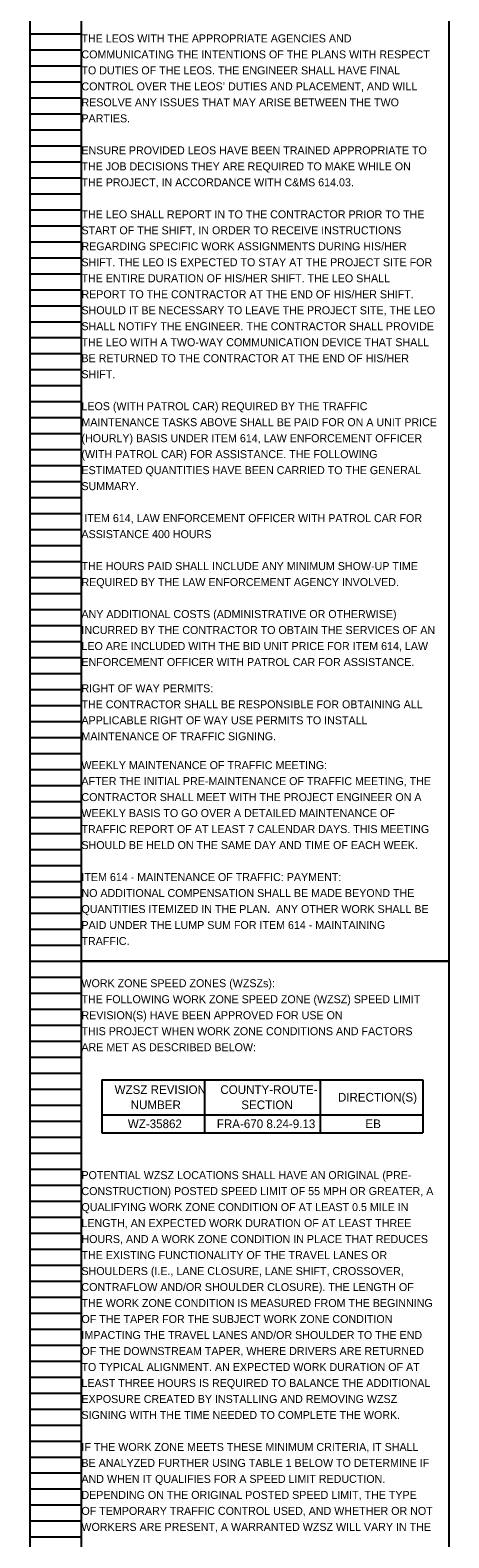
# Model space of a CAD drawing. Extents: x 16463 to 16500, y 5400 to 5823.
# Drawn here: x 16463.05 to 16470.39, y 5611.78 to 5638.18 of the extents above; entities that cross this region are included whole.
import ezdxf

# ---------------------------------------------------------------- set-up
doc = ezdxf.new("R2010")
doc.units = 0
for name, color, linetype in [('Default', 7, 'Continuous'), ('SC_Scratch1', 7, 'Continuous'), ('SH_Data', 7, 'Continuous')]:
    doc.layers.add(name, color=color, linetype=linetype)

msp = doc.modelspace()

# ---------------------------------------------------------------- linework, layer by layer
at = {"layer": 'Default'}
for p, q in [((16464.308, 5619.799), (16469.933, 5619.799)), ((16464.308, 5619.799), (16464.308, 5618.869)), ((16466.108, 5619.799), (16466.108, 5618.869)), ((16468.133, 5619.799), (16468.133, 5618.869)), ((16469.933, 5619.799), (16469.933, 5618.869)), ((16464.308, 5619.184), (16469.933, 5619.184)), ((16464.308, 5618.869), (16469.933, 5618.869))]:
    msp.add_line(p, q, dxfattribs=at)
at = {"layer": 'SC_Scratch1'}
for points in [[(16463.949, 5642.032), (16470.389, 5642.032), (16470.389, 5621.872), (16463.949, 5621.872)], [(16463.949, 5621.872), (16470.389, 5621.872), (16470.389, 5601.712), (16463.949, 5601.712)]]:
    msp.add_lwpolyline(points, close=True, dxfattribs=at)
at = {"layer": 'SH_Data'}
for p, q in [((16463.049, 5621.872), (16463.049, 5642.032)), ((16463.949, 5621.872), (16463.949, 5642.032)), ((16463.049, 5638.112), (16463.949, 5638.112)), ((16463.049, 5637.832), (16463.949, 5637.832)), ((16463.049, 5637.552), (16463.949, 5637.552)), ((16463.049, 5637.272), (16463.949, 5637.272)), ((16463.049, 5636.992), (16463.949, 5636.992)), ((16463.049, 5636.712), (16463.949, 5636.712)), ((16463.049, 5636.432), (16463.949, 5636.432)), ((16463.049, 5636.152), (16463.949, 5636.152)), ((16463.049, 5635.872), (16463.949, 5635.872)), ((16463.049, 5635.592), (16463.949, 5635.592)), ((16463.049, 5635.312), (16463.949, 5635.312)), ((16463.049, 5635.032), (16463.949, 5635.032)), ((16463.049, 5634.752), (16463.949, 5634.752)), ((16463.049, 5634.472), (16463.949, 5634.472)), ((16463.049, 5634.192), (16463.949, 5634.192)), ((16463.049, 5633.912), (16463.949, 5633.912)), ((16463.049, 5633.632), (16463.949, 5633.632)), ((16463.049, 5633.352), (16463.949, 5633.352)), ((16463.049, 5633.072), (16463.949, 5633.072)), ((16463.049, 5632.792), (16463.949, 5632.792)), ((16463.049, 5632.512), (16463.949, 5632.512)), ((16463.049, 5632.232), (16463.949, 5632.232)), ((16463.049, 5631.952), (16463.949, 5631.952)), ((16463.049, 5631.672), (16463.949, 5631.672)), ((16463.049, 5631.392), (16463.949, 5631.392)), ((16463.049, 5631.112), (16463.949, 5631.112)), ((16463.049, 5630.832), (16463.949, 5630.832)), ((16463.049, 5630.552), (16463.949, 5630.552)), ((16463.049, 5630.272), (16463.949, 5630.272)), ((16463.049, 5629.992), (16463.949, 5629.992)), ((16463.049, 5629.712), (16463.949, 5629.712)), ((16463.049, 5629.432), (16463.949, 5629.432)), ((16463.049, 5629.152), (16463.949, 5629.152)), ((16463.049, 5628.872), (16463.949, 5628.872)), ((16463.049, 5628.592), (16463.949, 5628.592)), ((16463.049, 5628.312), (16463.949, 5628.312)), ((16463.049, 5628.032), (16463.949, 5628.032)), ((16463.049, 5627.752), (16463.949, 5627.752)), ((16463.049, 5627.472), (16463.949, 5627.472)), ((16463.049, 5627.192), (16463.949, 5627.192)), ((16463.049, 5626.912), (16463.949, 5626.912)), ((16463.049, 5626.632), (16463.949, 5626.632)), ((16463.049, 5626.352), (16463.949, 5626.352)), ((16463.049, 5626.072), (16463.949, 5626.072)), ((16463.049, 5625.792), (16463.949, 5625.792)), ((16463.049, 5625.512), (16463.949, 5625.512)), ((16463.049, 5625.232), (16463.949, 5625.232)), ((16463.049, 5624.952), (16463.949, 5624.952)), ((16463.049, 5624.672), (16463.949, 5624.672)), ((16463.049, 5624.392), (16463.949, 5624.392)), ((16463.049, 5624.112), (16463.949, 5624.112)), ((16463.049, 5623.832), (16463.949, 5623.832)), ((16463.049, 5623.552), (16463.949, 5623.552)), ((16463.049, 5623.272), (16463.949, 5623.272)), ((16463.049, 5622.992), (16463.949, 5622.992)), ((16463.049, 5622.712), (16463.949, 5622.712)), ((16463.049, 5622.432), (16463.949, 5622.432)), ((16463.049, 5622.152), (16463.949, 5622.152)), ((16463.049, 5601.712), (16463.049, 5621.872)), ((16463.049, 5621.872), (16463.949, 5621.872)), ((16463.049, 5621.872), (16463.949, 5621.872)), ((16463.949, 5601.712), (16463.949, 5621.872)), ((16463.049, 5621.592), (16463.949, 5621.592)), ((16463.049, 5621.312), (16463.949, 5621.312)), ((16463.049, 5621.032), (16463.949, 5621.032)), ((16463.049, 5620.752), (16463.949, 5620.752)), ((16463.049, 5620.472), (16463.949, 5620.472)), ((16463.049, 5620.192), (16463.949, 5620.192)), ((16463.049, 5619.912), (16463.949, 5619.912)), ((16463.049, 5619.632), (16463.949, 5619.632)), ((16463.049, 5619.352), (16463.949, 5619.352)), ((16463.049, 5619.072), (16463.949, 5619.072)), ((16463.049, 5618.792), (16463.949, 5618.792)), ((16463.049, 5618.512), (16463.949, 5618.512)), ((16463.049, 5618.232), (16463.949, 5618.232)), ((16463.049, 5617.952), (16463.949, 5617.952)), ((16463.049, 5617.672), (16463.949, 5617.672)), ((16463.049, 5617.392), (16463.949, 5617.392)), ((16463.049, 5617.112), (16463.949, 5617.112)), ((16463.049, 5616.832), (16463.949, 5616.832)), ((16463.049, 5616.552), (16463.949, 5616.552)), ((16463.049, 5616.272), (16463.949, 5616.272)), ((16463.049, 5615.992), (16463.949, 5615.992)), ((16463.049, 5615.712), (16463.949, 5615.712)), ((16463.049, 5615.432), (16463.949, 5615.432)), ((16463.049, 5615.152), (16463.949, 5615.152)), ((16463.049, 5614.872), (16463.949, 5614.872)), ((16463.049, 5614.592), (16463.949, 5614.592)), ((16463.049, 5614.312), (16463.949, 5614.312)), ((16463.049, 5614.032), (16463.949, 5614.032)), ((16463.049, 5613.752), (16463.949, 5613.752)), ((16463.049, 5613.472), (16463.949, 5613.472)), ((16463.049, 5613.192), (16463.949, 5613.192)), ((16463.049, 5612.912), (16463.949, 5612.912)), ((16463.049, 5612.632), (16463.949, 5612.632)), ((16463.049, 5612.352), (16463.949, 5612.352)), ((16463.049, 5612.072), (16463.949, 5612.072)), ((16463.049, 5611.792), (16463.949, 5611.792))]:
    msp.add_line(p, q, dxfattribs=at)

# ---------------------------------------------------------------- texts
at = {"layer": 'Default'}
for s, height, p in [('THE LEOS WITH THE APPROPRIATE AGENCIES AND ', 0.14, (16463.949, 5637.962)), ('COMMUNICATING THE INTENTIONS OF THE PLANS WITH RESPECT ', 0.14, (16463.949, 5637.682)), ('TO DUTIES OF THE LEOS. THE ENGINEER SHALL HAVE FINAL ', 0.14, (16463.949, 5637.402)), ('CONTROL OVER THE LEOS’ DUTIES AND PLACEMENT, AND WILL ', 0.14, (16463.949, 5637.122)), ('RESOLVE ANY ISSUES THAT MAY ARISE BETWEEN THE TWO ', 0.14, (16463.949, 5636.842)), ('PARTIES. ', 0.14, (16463.949, 5636.562)), ('ENSURE PROVIDED LEOS HAVE BEEN TRAINED APPROPRIATE TO ', 0.14, (16463.949, 5636.002)), ('THE JOB DECISIONS THEY ARE REQUIRED TO MAKE WHILE ON ', 0.14, (16463.949, 5635.722)), ('THE PROJECT, IN ACCORDANCE WITH C&MS 614.03. ', 0.14, (16463.949, 5635.442)), ('THE LEO SHALL REPORT IN TO THE CONTRACTOR PRIOR TO THE ', 0.14, (16463.949, 5634.882)), ('START OF THE SHIFT, IN ORDER TO RECEIVE INSTRUCTIONS ', 0.14, (16463.949, 5634.602)), ('REGARDING SPECIFIC WORK ASSIGNMENTS DURING HIS/HER ', 0.14, (16463.949, 5634.322)), ('SHIFT. THE LEO IS EXPECTED TO STAY AT THE PROJECT SITE FOR ', 0.14, (16463.949, 5634.042)), ('THE ENTIRE DURATION OF HIS/HER SHIFT. THE LEO SHALL ', 0.14, (16463.949, 5633.762)), ('REPORT TO THE CONTRACTOR AT THE END OF HIS/HER SHIFT. ', 0.14, (16463.949, 5633.482)), ('SHOULD IT BE NECESSARY TO LEAVE THE PROJECT SITE, THE LEO ', 0.14, (16463.949, 5633.202)), ('SHALL NOTIFY THE ENGINEER. THE CONTRACTOR SHALL PROVIDE ', 0.14, (16463.949, 5632.922)), ('THE LEO WITH A TWO-WAY COMMUNICATION DEVICE THAT SHALL ', 0.14, (16463.949, 5632.642)), ('BE RETURNED TO THE CONTRACTOR AT THE END OF HIS/HER ', 0.14, (16463.949, 5632.362)), ('SHIFT.', 0.14, (16463.949, 5632.082)), ('LEOS (WITH PATROL CAR) REQUIRED BY THE TRAFFIC ', 0.14, (16463.949, 5631.522)), ('MAINTENANCE TASKS ABOVE SHALL BE PAID FOR ON A UNIT PRICE ', 0.14, (16463.949, 5631.242)), ('(HOURLY) BASIS UNDER ITEM 614, LAW ENFORCEMENT OFFICER ', 0.14, (16463.949, 5630.962)), ('(WITH PATROL CAR) FOR ASSISTANCE. THE FOLLOWING ', 0.14, (16463.949, 5630.682)), ('ESTIMATED QUANTITIES HAVE BEEN CARRIED TO THE GENERAL ', 0.14, (16463.949, 5630.402)), ('SUMMARY.', 0.14, (16463.949, 5630.122)), (' ITEM 614, LAW ENFORCEMENT OFFICER WITH PATROL CAR FOR ', 0.14, (16463.949, 5629.562)), ('ASSISTANCE 400 HOURS ', 0.14, (16463.949, 5629.282)), ('THE HOURS PAID SHALL INCLUDE ANY MINIMUM SHOW-UP TIME ', 0.14, (16463.949, 5628.722)), ('REQUIRED BY THE LAW ENFORCEMENT AGENCY INVOLVED. ', 0.14, (16463.949, 5628.442)), ('ANY ADDITIONAL COSTS (ADMINISTRATIVE OR OTHERWISE) ', 0.14, (16463.949, 5627.882)), ('INCURRED BY THE CONTRACTOR TO OBTAIN THE SERVICES OF AN ', 0.14, (16463.949, 5627.602)), ('LEO ARE INCLUDED WITH THE BID UNIT PRICE FOR ITEM 614, LAW ', 0.14, (16463.949, 5627.322)), ('ENFORCEMENT OFFICER WITH PATROL CAR FOR ASSISTANCE.', 0.14, (16463.949, 5627.042)), ('RIGHT OF WAY PERMITS:', 0.14, (16463.949, 5626.582)), ('THE CONTRACTOR SHALL BE RESPONSIBLE FOR OBTAINING ALL ', 0.14, (16463.949, 5626.302)), ('APPLICABLE RIGHT OF WAY USE PERMITS TO INSTALL ', 0.14, (16463.949, 5626.022)), ('MAINTENANCE OF TRAFFIC SIGNING.', 0.14, (16463.949, 5625.742)), ('WEEKLY MAINTENANCE OF TRAFFIC MEETING:', 0.14, (16463.949, 5625.237)), ('AFTER THE INITIAL PRE-MAINTENANCE OF TRAFFIC MEETING, THE ', 0.14, (16463.949, 5624.957)), ('CONTRACTOR SHALL MEET WITH THE PROJECT ENGINEER ON A ', 0.14, (16463.949, 5624.677)), ('WEEKLY BASIS TO GO OVER A DETAILED MAINTENANCE OF ', 0.14, (16463.949, 5624.397)), ('TRAFFIC REPORT OF AT LEAST 7 CALENDAR DAYS. THIS MEETING ', 0.14, (16463.949, 5624.117)), ('SHOULD BE HELD ON THE SAME DAY AND TIME OF EACH WEEK.', 0.14, (16463.949, 5623.837)), ('ITEM 614 - MAINTENANCE OF TRAFFIC: PAYMENT:', 0.14, (16463.949, 5623.277)), ('NO ADDITIONAL COMPENSATION SHALL BE MADE BEYOND THE ', 0.14, (16463.949, 5622.997)), ('QUANTITIES ITEMIZED IN THE PLAN.  ANY OTHER WORK SHALL BE ', 0.14, (16463.949, 5622.717)), ('PAID UNDER THE LUMP SUM FOR ITEM 614 - MAINTAINING ', 0.14, (16463.949, 5622.437)), ('TRAFFIC.', 0.14, (16463.949, 5622.157)), ('WORK ZONE SPEED ZONES (WZSZs):', 0.14, (16463.949, 5621.418)), ('THE FOLLOWING WORK ZONE SPEED ZONE (WZSZ) SPEED LIMIT ', 0.14, (16463.949, 5621.138)), ('REVISION(S) HAVE BEEN APPROVED FOR USE ON', 0.14, (16463.949, 5620.858)), ('THIS PROJECT WHEN WORK ZONE CONDITIONS AND FACTORS ', 0.14, (16463.949, 5620.578)), ('ARE MET AS DESCRIBED BELOW: ', 0.14, (16463.949, 5620.298)), ('WZSZ REVISION ', 0.1518, (16464.53, 5619.549)), ('COUNTY-ROUTE-', 0.1518, (16466.384, 5619.549)), ('DIRECTION(S)', 0.1518, (16468.444, 5619.416)), ('NUMBER', 0.1518, (16464.812, 5619.283)), ('SECTION', 0.1518, (16466.751, 5619.283)), ('WZ-35862', 0.1518, (16464.762, 5618.951)), ('FRA-670 8.24-9.13', 0.1518, (16466.322, 5618.951)), ('EB', 0.1518, (16468.927, 5618.951)), ('POTENTIAL WZSZ LOCATIONS SHALL HAVE AN ORIGINAL (PRE-', 0.14, (16463.949, 5618.058)), ('CONSTRUCTION) POSTED SPEED LIMIT OF 55 MPH OR GREATER, A ', 0.14, (16463.949, 5617.778)), ('QUALIFYING WORK ZONE CONDITION OF AT LEAST 0.5 MILE IN ', 0.14, (16463.949, 5617.498)), ('LENGTH, AN EXPECTED WORK DURATION OF AT LEAST THREE ', 0.14, (16463.949, 5617.218)), ('HOURS, AND A WORK ZONE CONDITION IN PLACE THAT REDUCES ', 0.14, (16463.949, 5616.938)), ('THE EXISTING FUNCTIONALITY OF THE TRAVEL LANES OR ', 0.14, (16463.949, 5616.658)), ('SHOULDERS (I.E., LANE CLOSURE, LANE SHIFT, CROSSOVER, ', 0.14, (16463.949, 5616.378)), ('CONTRAFLOW AND/OR SHOULDER CLOSURE). THE LENGTH OF ', 0.14, (16463.949, 5616.098)), ('THE WORK ZONE CONDITION IS MEASURED FROM THE BEGINNING ', 0.14, (16463.949, 5615.818)), ('OF THE TAPER FOR THE SUBJECT WORK ZONE CONDITION ', 0.14, (16463.949, 5615.538)), ('IMPACTING THE TRAVEL LANES AND/OR SHOULDER TO THE END ', 0.14, (16463.949, 5615.258)), ('OF THE DOWNSTREAM TAPER, WHERE DRIVERS ARE RETURNED ', 0.14, (16463.949, 5614.978)), ('TO TYPICAL ALIGNMENT. AN EXPECTED WORK DURATION OF AT ', 0.14, (16463.949, 5614.698)), ('LEAST THREE HOURS IS REQUIRED TO BALANCE THE ADDITIONAL ', 0.14, (16463.949, 5614.418)), ('EXPOSURE CREATED BY INSTALLING AND REMOVING WZSZ ', 0.14, (16463.949, 5614.138)), ('SIGNING WITH THE TIME NEEDED TO COMPLETE THE WORK. ', 0.14, (16463.949, 5613.858)), ('IF THE WORK ZONE MEETS THESE MINIMUM CRITERIA, IT SHALL ', 0.14, (16463.949, 5613.298)), ('BE ANALYZED FURTHER USING TABLE 1 BELOW TO DETERMINE IF ', 0.14, (16463.949, 5613.018)), ('AND WHEN IT QUALIFIES FOR A SPEED LIMIT REDUCTION. ', 0.14, (16463.949, 5612.738)), ('DEPENDING ON THE ORIGINAL POSTED SPEED LIMIT, THE TYPE ', 0.14, (16463.949, 5612.458)), ('OF TEMPORARY TRAFFIC CONTROL USED, AND WHETHER OR NOT ', 0.14, (16463.949, 5612.178)), ('WORKERS ARE PRESENT, A WARRANTED WZSZ WILL VARY IN THE ', 0.14, (16463.949, 5611.898))]:
    msp.add_text(s, height=height, dxfattribs=at).set_placement(p)

doc.saveas('drawing.dxf')
